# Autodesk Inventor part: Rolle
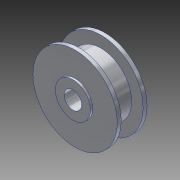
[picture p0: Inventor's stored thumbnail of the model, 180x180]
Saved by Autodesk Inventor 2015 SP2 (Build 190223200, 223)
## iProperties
Created: 2012-07
Part Number: Rolle
Material: Aluminium 6061
Document SubType Name: Modeling
Designer: rYan
Density: 2.71 g/cm^3
Mass: 0.359243 g
Surface Area: 2.97309 cm^2
Volume: 0.132562 cm^3
Appearance: Aluminium - flach
Author: rYan
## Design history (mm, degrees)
sketch "Skizze1"
  geometry: L1 (0, -1.95)-(0, 1.95); L2 (0, 1.95)-(2, 1.95); L3 (4.8, 1.7)-(4.8, 1.25); L4 (4.8, 1.25)-(3.5, 1.25); L5 (3.5, 1.25)-(3.5, -1.25); L6 (3.5, -1.25)-(4.8, -1.25); L7 (4.8, -1.25)-(4.8, -1.7); L8 (2, -1.95)-(0, -1.95); L9 (-0.96, 0)-(5.76, 0) reference; L10 (0, 2.73)-(0, -2.73) reference; L11 (2, 1.95)-(2, 1.7); L12 (2, 1.7)-(4.8, 1.7); L13 (2, -1.95)-(2, -1.7); L14 (2, -1.7)-(4.8, -1.7); 1 further point
  constraints: 24 end point, 6 parallel, 3 perpendicular, 3 vertical, 1 collinear, 5 other
  dimensions: "d3" = 3.9 distance between parallel lines of L8 L2; "d4" = 2.5 distance between parallel lines of L6 L4; "d5" = 1.3 distance between parallel lines of L3 L5; "d16" = 7 diameter of L5 L1; "d17" = 4 diameter of L11 L1; "d18" = 0.25 distance between parallel lines of L2 L12
revolve "Umdrehung1" sketch "Skizze1" stored, may be unused: angle "d8" = 90 deg
sketch "Skizze2"
  geometry: 1 further point
hole "Bohrung1" sketch "Skizze2" at (0, 0) diameter "d9" = 2; stored, may be unused: countersink angle "d13" = 90 deg, drill point angle "d15" = 118 deg; dims "d10" = 6, "d11" = 4, "d12" = 2, "d14" = 8
node "Volumenkörper1"
